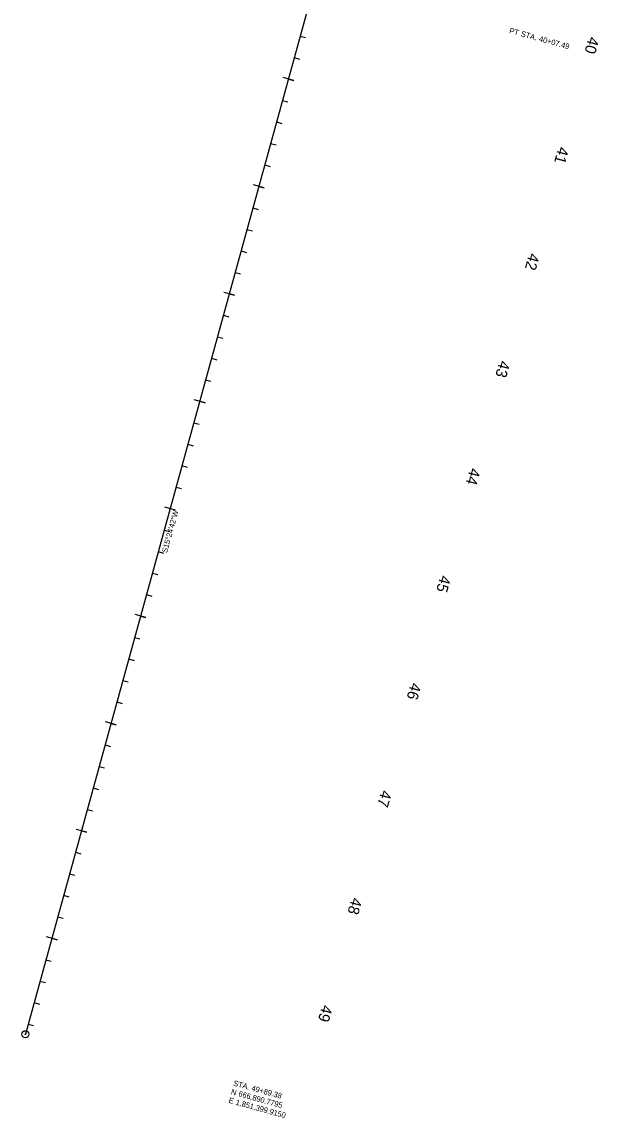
# Model space of a CAD drawing. Extents: x 1849564 to 1851966, y 666816 to 670715.
# Drawn here: x 1851397 to 1851915, y 666816 to 667799 of the extents above; entities that cross this region are included whole.
import ezdxf

# ---------------------------------------------------------------- set-up
doc = ezdxf.new("R2010")
doc.units = 0
for name, color, linetype in [('CONCEPT - PAVEMENT MARKING - Crosswalk Long', 7, 'Continuous'), ('CONCEPT - PAVEMENT MARKING - Crosswalk Parallel', 7, 'Continuous'), ('CONCEPT - PAVEMENT MARKING - Stop Bar', 7, 'Continuous'), ('CONCEPT - PAVEMENT MARKING - Striping - Yellow', 7, 'Continuous'), ('Default', 7, 'Continuous'), ('DES - DRG - Special Ditches', 7, 'Continuous')]:
    doc.layers.add(name, color=color, linetype=linetype)

msp = doc.modelspace()

# ---------------------------------------------------------------- linework, layer by layer
at = {"layer": 'CONCEPT - PAVEMENT MARKING - Stop Bar'}
for p, q in [((1851646.9, 667786.74), (1851651.7, 667785.42)), ((1851641.58, 667767.46), (1851646.39, 667766.14)), ((1851641.09, 667746.85), (1851631.45, 667749.51)), ((1851630.95, 667728.9), (1851635.76, 667727.58)), ((1851625.64, 667709.62), (1851630.44, 667708.3)), ((1851620.32, 667690.34), (1851625.13, 667689.02)), ((1851615.01, 667671.06), (1851619.81, 667669.73)), ((1851614.51, 667650.45), (1851604.87, 667653.11)), ((1851604.38, 667632.5), (1851609.18, 667631.17)), ((1851599.06, 667613.22), (1851603.87, 667611.89)), ((1851593.75, 667593.93), (1851598.55, 667592.61)), ((1851588.43, 667574.65), (1851593.23, 667573.33)), ((1851587.94, 667554.04), (1851578.3, 667556.7)), ((1851577.8, 667536.09), (1851582.6, 667534.77)), ((1851572.49, 667516.81), (1851577.29, 667515.49)), ((1851567.17, 667497.53), (1851571.97, 667496.21)), ((1851561.86, 667478.25), (1851566.66, 667476.93)), ((1851561.36, 667457.64), (1851551.72, 667460.3)), ((1851551.23, 667439.69), (1851556.03, 667438.36)), ((1851545.91, 667420.41), (1851550.71, 667419.08)), ((1851540.6, 667401.13), (1851545.4, 667399.8)), ((1851535.28, 667381.85), (1851540.08, 667380.52)), ((1851534.79, 667361.24), (1851525.15, 667363.89)), ((1851524.65, 667343.28), (1851529.45, 667341.96)), ((1851519.34, 667324), (1851524.14, 667322.68)), ((1851514.02, 667304.72), (1851518.82, 667303.4)), ((1851508.71, 667285.44), (1851513.51, 667284.12)), ((1851508.21, 667264.83), (1851498.57, 667267.49)), ((1851498.08, 667246.88), (1851502.88, 667245.56)), ((1851492.76, 667227.6), (1851497.56, 667226.28)), ((1851487.45, 667208.32), (1851492.25, 667206.99)), ((1851482.13, 667189.04), (1851486.93, 667187.71)), ((1851481.64, 667168.43), (1851472, 667171.09)), ((1851471.5, 667150.48), (1851476.3, 667149.15)), ((1851466.19, 667131.19), (1851470.99, 667129.87)), ((1851460.87, 667111.91), (1851465.67, 667110.59)), ((1851455.56, 667092.63), (1851460.36, 667091.31)), ((1851455.06, 667072.02), (1851445.42, 667074.68)), ((1851444.93, 667054.07), (1851449.73, 667052.75)), ((1851439.61, 667034.79), (1851444.41, 667033.47)), ((1851434.3, 667015.51), (1851439.1, 667014.19)), ((1851428.98, 666996.23), (1851433.78, 666994.91)), ((1851428.49, 666975.62), (1851418.85, 666978.28)), ((1851418.35, 666957.67), (1851423.15, 666956.34)), ((1851413.04, 666938.39), (1851417.84, 666937.06)), ((1851407.72, 666919.11), (1851412.52, 666917.78)), ((1851402.41, 666899.82), (1851407.21, 666898.5))]:
    msp.add_line(p, q, dxfattribs=at)
at = {"layer": 'CONCEPT - PAVEMENT MARKING - Striping - Yellow'}
for p, q in [((1851636.27, 667748.18), (1851641.07, 667746.86)), ((1851609.69, 667651.78), (1851614.5, 667650.45)), ((1851583.12, 667555.37), (1851587.92, 667554.05)), ((1851556.54, 667458.97), (1851561.34, 667457.65)), ((1851534.79, 667361.24), (1851525.13, 667363.9)), ((1851503.39, 667266.16), (1851508.19, 667264.84)), ((1851476.82, 667169.76), (1851481.62, 667168.43)), ((1851450.24, 667073.35), (1851455.04, 667072.03)), ((1851423.67, 666976.95), (1851428.47, 666975.62))]:
    msp.add_line(p, q, dxfattribs=at)
for radius in [3.14, 0.33]:
    msp.add_circle((1851399.91, 666890.78), radius, dxfattribs=at)
at = {"layer": 'Default'}
msp.add_line((1851660.85, 667837.37), (1851399.91, 666890.78), dxfattribs=at)
at = {"layer": 'DES - DRG - Special Ditches'}
msp.add_line((1851660.85, 667837.37), (1851399.91, 666890.78), dxfattribs=at)

# ---------------------------------------------------------------- texts
at = {"layer": 'CONCEPT - PAVEMENT MARKING - Crosswalk Long'}
for s, p in [('PT', (1851834.38, 667789.53)), (' STA. ', (1851842.96, 667787.17)), ('40+07.49', (1851861.09, 667782.17))]:
    msp.add_text(s, height=4.98, rotation=344.58842, dxfattribs=at).set_placement(p)
at = {"layer": 'CONCEPT - PAVEMENT MARKING - Crosswalk Parallel'}
for s, rotation, p in [('S15°24\'42"W', 74.58842, (1851527.2, 667322.5)), ('N ', 344.58842, (1851584.26, 666837.03)), ('STA. ', 344.58842, (1851586.38, 666844.71)), ('49+89.38', 344.58842, (1851602.65, 666840.22)), ('E ', 344.58842, (1851582.14, 666829.34)), ('1,851,399.9150', 344.58842, (1851588.48, 666827.6)), ('666,890.7795', 344.58842, (1851590.97, 666835.18))]:
    msp.add_text(s, height=4.98, rotation=rotation, dxfattribs=at).set_placement(p)
at = {"layer": 'CONCEPT - PAVEMENT MARKING - Stop Bar'}
for s, rotation, p in [('40', 254.92545, (1851906.15, 667786.72)), ('41', 254.58842, (1851879, 667687.97)), ('42', 254.58842, (1851852.66, 667592.44)), ('43', 254.58842, (1851826.1, 667496.09)), ('44', 254.58842, (1851799.52, 667399.66)), ('45', 254.58842, (1851772.96, 667303.32)), ('46', 254.58842, (1851746.38, 667206.88)), ('47', 254.58842, (1851719.8, 667110.47)), ('48', 254.58842, (1851693.23, 667014.08)), ('49', 254.58842, (1851666.65, 666917.67))]:
    msp.add_text(s, height=9.96, rotation=rotation, dxfattribs=at).set_placement(p)
at = {"layer": 'CONCEPT - PAVEMENT MARKING - Striping - Yellow'}
for s, rotation, p in [('40', 254.92545, (1851906.15, 667786.72)), ('45', 254.58842, (1851772.96, 667303.32))]:
    msp.add_text(s, height=9.96, rotation=rotation, dxfattribs=at).set_placement(p)

doc.saveas('drawing.dxf')
